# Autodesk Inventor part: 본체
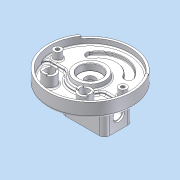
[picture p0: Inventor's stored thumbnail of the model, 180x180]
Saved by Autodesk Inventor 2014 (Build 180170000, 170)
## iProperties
Company: 한국ATC센터
Created: 2015-04
Part Number: 본체
Document SubType Name: Modeling
Designer: KYOUNG IL JANG
Density: 1 g/cm^3
Material: 일반
Mass: 494.771 g
Surface Area: 1387.34 cm^2
Volume: 494.771 cm^3
Appearance: 매끄러움 - 흰색
Author: KYOUNG IL JANG
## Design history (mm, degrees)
sketch "스케치1"
  geometry: L1 (-59, -19)-(-59, 19); L2 (59, 19)-(59, -19); L3 (-41, 19)-(-41, -19); L4 (41, -19)-(41, 19); L5 (38.527, 33.023)-(55.442, 39.179); L6 (-38.527, 33.023)-(-55.442, 39.179); C1 r 90 at (0, 0); C2 r 95 at (0, 0); A1 r 59 centre (0, 19) between (59, 19) and (-59, 19); A2 r 59 centre (0, -19) between (-59, -19) and (59, -19); A3 r 41 centre (0, -19) between (-41, -19) and (41, -19); A4 r 41 centre (0, 19) between (41, 19) and (-41, 19); 2 further points
  constraints: 12 end point, 12 point on circle, 6 centre point, 4 tangent, 2 parallel, 2 point on line, 1 coincident, 1 horizontal alignment, 1 midpoint, 1 vertical, 1 vertical alignment, 3 other
  dimensions: "d2" = 180 diameter of C1; "d3" = 156 dimension on A2 A1; "d4" = 118 distance between parallel lines of L2 L1; "d5" = 18 distance between parallel lines of L2 L4; "d8" = 190 diameter of C2; "d124" = 110 deg dimension on A1.centre point (0, 0) L5.end; "d125" = 140 deg angle of L5 L6
extrude "돌출1" new body sketch "스케치1" distance "d6" = 14; taper "d7" = 0 deg
extrude "돌출2" join sketch "스케치1" distance "d9" = 13; taper "d10" = 0 deg
extrude "돌출3" cut sketch "스케치1" distance "d11" = 7; taper "d12" = 0 deg
sketch "스케치2"
  geometry: C1 r 11.5 at (0, 0); 1 further point
  constraints: 1 centre point, 1 coincident
  dimensions: "d13" = 23 diameter of C1
extrude "돌출4" cut sketch "스케치2" stored distance "d14" = 7; taper "d15" = 0 deg
fillet "모깎기1"
fillet "모깎기2"
sketch "스케치3"
  geometry: L1 (-73.724, 51.622)-(-77.819, 54.49); L2 (73.724, 51.622)-(77.819, 54.49); L3 (0, 0)-(0, -90); A1 r 95 centre (0, 0) between (-77.819, 54.49) and (77.819, 54.49) reference; A2 r 90 centre (0, 0) between (-73.724, 51.622) and (73.724, 51.622) reference; 1 further point
  constraints: 6 end point, 5 point on circle, 1 point on line, 1 vertical, 1 other
  dimensions: "d16" = 250 deg dimension on L2 L1
extrude "돌출5" join sketch "스케치3" distance "d17" = 5; taper "d18" = 0 deg
hole "구멍1" diameter "d21" = 50; stored, may be unused: countersink angle "d25" = 90 deg, drill point angle "d27" = 0 deg; dims "d19" = 10, "d20" = 10, "d22" = 6, "d23" = 4, "d24" = 2, "d26" = 5
fillet "모깎기3" dims "d28" = 0.3
fillet "모깎기5" dims "d30" = 3
sketch "스케치4"
  geometry: C1 r 35 at (0, 0); C2 r 25 at (0, 0); 1 further point
  constraints: 2 centre point, 1 coincident
  dimensions: "d32" = 70 diameter of C1 (derived); "d36" = 10 radial gap between concentric circles of C1 C2
extrude "돌출6" join sketch "스케치4" distance "d33" = 10; taper "d34" = 0 deg
feature "면 기울기2" dims angle "d37" = 10 deg
chamfer "모따기1" distance "d39" = 1; stored, may be unused: second distance "d40" = 2, angle "d41" = 45 deg
fillet "모깎기7" dims "d42" = 5
sketch "스케치5"
  geometry: L1 (-40.249, -12)-(-89.196, -12); L2 (40.249, -12)-(89.196, -12); A1 r 90 centre (0, 0) between (-89.196, -12) and (89.196, -12) reference; A2 r 42 centre (0, 0) between (-40.249, -12) and (40.249, -12); 1 further point
  constraints: 4 end point, 4 point on circle, 1 centre point, 1 collinear, 1 horizontal, 1 point on line
  dimensions: "d43" = 48 radial gap between concentric circles of A1 A2; "d44" = 12 distance from line of point (0, 0) L1
extrude "돌출7" cut sketch "스케치5" stored distance "d45" = 10; taper "d46" = 0 deg
fillet "모깎기8" dims "d47" = 10
chamfer "모따기2" distance "d49" = 1; stored, may be unused: second distance "d50" = 2, angle "d51" = 45 deg
sketch "스케치8"
  geometry: C1 r 9 at (74, 0); C2 r 9 at (-74, 0); A1 r 74 centre (0, 0) between (74, 0) and (-74, 0); 1 further point
  constraints: 3 centre point, 2 horizontal alignment, 2 point on circle, 1 coincident, 1 equal radius
  dimensions: "d64" = 18 diameter of C1; "d65" = 148 diameter of A1
extrude "돌출9" join sketch "스케치8" stored distance "d66" = 5; taper "d67" = 0 deg
sketch "스케치11"
  geometry: C1 r 15 at (40, -52); C2 r 15 at (-40, -52); 1 further point
  constraints: 2 centre point, 1 equal radius, 1 horizontal alignment
  dimensions: "d82" = 52 vertical distance of point (0, 0) C1.centre; "d83" = 30 diameter of C1; "d84" = 80 distance of C2.centre C1.centre; "d85" = 40 horizontal distance of point (0, 0) C1.centre (= 0.5 x d84)
extrude "돌출10" join sketch "스케치11" stored distance "d86" = 10; taper "d87" = 0 deg
node "구멍3"
node "구멍5"
hole "구멍6" diameter "d92" = 20; stored, may be unused: countersink angle "d96" = 90 deg, drill point angle "d98" = 118 deg; dims "d90" = 10, "d91" = 10, "d93" = 6, "d94" = 4, "d95" = 2, "d97" = 8
hole "구멍7" diameter "d101" = 20; stored, may be unused: countersink angle "d105" = 90 deg, drill point angle "d107" = 118 deg; dims "d99" = 10, "d100" = 10, "d102" = 6, "d103" = 4, "d104" = 2, "d106" = 8
fillet "모깎기13" dims "d108" = 3
sketch "스케치13"
  geometry: L1 (-20.252, -58)-(-26, -58); L2 (-42, -58)-(-47.748, -58); L3 (-20.252, -46)-(-26, -46); L4 (-42, -46)-(-47.748, -46); L5 (-108, -65.748)-(-108, -60); L6 (-108, -44)-(-108, -38.252); L7 (-120, -44)-(-120, -38.252); L8 (-120, -60)-(-120, -65.748); A1 r 15 centre (-34, -52) between (-20.252, -58) and (-47.748, -58) reference; A2 r 10 centre (-34, -52) between (-26, -58) and (-42, -58) reference; A3 r 15 centre (-114, -52) between (-108, -65.748) and (-108, -38.252) reference; A4 r 10 centre (-114, -52) between (-108, -60) and (-108, -44) reference; 1 further point
  constraints: 16 end point, 16 point on circle, 3 equal length, 3 point on line, 2 collinear, 1 horizontal, 1 perpendicular
  dimensions: "d114" = 12 distance between parallel lines of L4 L2; "d115" = 6 distance from line of A1.centre L2 (= 0.5 x d114); "d116" = 12 distance between parallel lines of L8 L5 (= d114); "d117" = 6 distance from line of A3.centre L5 (= d115)
extrude "돌출12" join sketch "스케치13" distance "d118" = 3; taper "d119" = 0 deg
fillet "모깎기14" dims "d120" = 1
sketch "스케치14"
  geometry: L1 (23, 32.5)-(-53, 32.5); L2 (-65, 20.5)-(-65, -20.5); L3 (-53, -32.5)-(23, -32.5); L4 (35, -20.5)-(35, 20.5); L5 (30, 20.5)-(30, -20.5); L6 (23, -27.5)-(-53, -27.5); L7 (-60, -20.5)-(-60, 20.5); L8 (-53, 27.5)-(23, 27.5); A1 r 12 centre (-53, -20.5) between (-65, -20.5) and (-53, -32.5); A2 r 12 centre (-53, 20.5) between (-53, 32.5) and (-65, 20.5); A3 r 12 centre (23, 20.5) between (35, 20.5) and (23, 32.5); A4 r 12 centre (23, -20.5) between (23, -32.5) and (35, -20.5); A5 r 7 centre (23, -20.5) between (23, -27.5) and (30, -20.5); A6 r 7 centre (-53, -20.5) between (-60, -20.5) and (-53, -27.5); A7 r 7 centre (-53, 20.5) between (-53, 27.5) and (-60, 20.5); A8 r 7 centre (23, 20.5) between (30, 20.5) and (23, 27.5); A9 r 6 centre (-23, -25) between (-17.546, -27.5) and (-28.454, -27.5); A10 r 6 centre (-23, 25) between (-28.454, 27.5) and (-17.546, 27.5); 6 further points
  constraints: 20 point on circle, 16 end point, 12 point on line, 10 centre point, 8 tangent, 4 equal radius, 4 parallel, 2 perpendicular, 1 horizontal, 1 horizontal alignment, 1 midpoint, 1 vertical alignment, 7 other
  dimensions: "d126" = 35 distance from line of point (0, 0) L4; "d127" = 65 distance of point (35, -32.5) point (35, 32.5); "d128" = 100 distance of point (35, 32.5) point (-65, 32.5); "d132" = 12 radius of A1; "d133" = 5 distance between parallel lines of L5 L4; "d141" = 42 distance from line of A9.centre L2; "d142" = 12 diameter of A9; "d143" = 50 distance of A10.centre A9.centre; "d144" = 25 vertical distance of point (0, 0) A9.centre (= 0.5 x d143)
extrude "돌출13" join sketch "스케치14" distance "d130" = 58; taper "d131" = 0 deg
fillet "모깎기16" dims "d145" = 3
hole "구멍8" diameter "d148" = 4.134; stored, may be unused: countersink angle "d152" = 90 deg, drill point angle "d154" = 118 deg; dims "d146" = 10, "d147" = 10, "d149" = 12, "d150" = 4, "d151" = 2, "d153" = 15
hole "구멍9" diameter "d157" = 4.134; stored, may be unused: countersink angle "d161" = 90 deg, drill point angle "d163" = 118 deg; dims "d155" = 10, "d156" = 10, "d158" = 12, "d159" = 4, "d160" = 2, "d162" = 15
sketch "스케치17"
  geometry: L1 (-58, 110.5)-(-58, -69.5) reference; C1 r 15 at (-29.5, 20.5); 1 further point
  constraints: 1 centre point, 1 horizontal alignment
  dimensions: "d164" = 28.5 distance from line of C1.centre L1; "d165" = 30 diameter of C1
extrude "돌출16" join sketch "스케치17" distance "d166" = 28; taper "d167" = 0 deg
fillet "모깎기17" dims "d168" = 1
hole "구멍10" diameter "d171" = 22; stored, may be unused: countersink angle "d175" = 90 deg, drill point angle "d177" = 118 deg; dims "d169" = 10, "d170" = 10, "d172" = 12, "d173" = 26, "d174" = 4, "d176" = 15
node "솔리드1"
sketch "스케치9"
  geometry: 1 further point
hole "구멍2" sketch "스케치9" diameter "d68" = 8.376; stored, may be unused: countersink angle "d72" = 90 deg, drill point angle "d74" = 120 deg; dims "d69" = 16, "d70" = 4, "d71" = 2, "d73" = 21
sketch "스케치10"
  geometry: 1 further point
hole "구멍4" sketch "스케치10" diameter "d75" = 8.376; stored, may be unused: countersink angle "d79" = 90 deg, drill point angle "d81" = 120 deg; dims "d76" = 16, "d77" = 4, "d78" = 2, "d80" = 21
